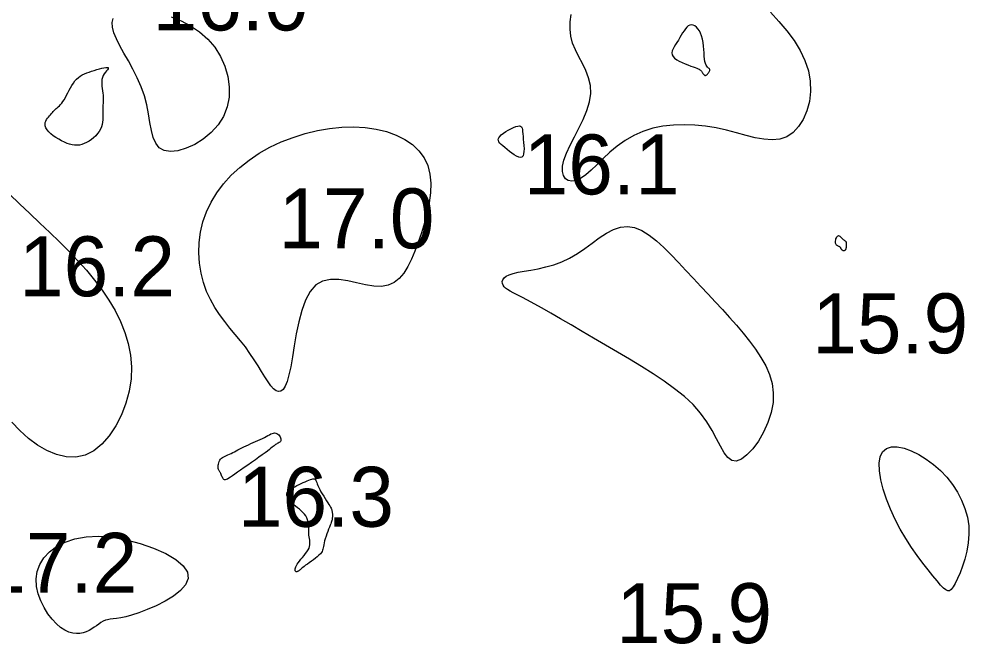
# Model space of a CAD drawing. Extents: x 3040093 to 3056816, y 408076 to 509144.
# Drawn here: x 3045772.1 to 3045851.4, y 434457.7 to 434509.8 of the extents above; entities that cross this region are included whole.
import ezdxf

# ---------------------------------------------------------------- set-up
doc = ezdxf.new("R2010")
doc.units = 0
doc.layers.add('V-CHAN-CONT-EL17', color=7, linetype='Continuous')
doc.layers.add('V-TOPO-SOUN-0610', color=7, linetype='Continuous')

msp = doc.modelspace()

# ---------------------------------------------------------------- linework, layer by layer
at = {"layer": 'V-CHAN-CONT-EL17'}
for points in [[(3045784.771, 434510.028), (3045785.592, 434509.693), (3045786.39, 434509.275), (3045787.141, 434508.769), (3045787.819, 434508.172), (3045788.402, 434507.485), (3045788.881, 434506.722), (3045789.247, 434505.905), (3045789.493, 434505.054), (3045789.613, 434504.19), (3045789.597, 434503.333), (3045789.44, 434502.503), (3045789.133, 434501.722), (3045788.677, 434501.007), (3045788.1, 434500.371), (3045787.44, 434499.827), (3045786.733, 434499.385), (3045786.016, 434499.057), (3045785.325, 434498.854), (3045784.698, 434498.787), (3045784.171, 434498.868), (3045783.769, 434499.102), (3045783.478, 434499.474), (3045783.269, 434499.964), (3045783.117, 434500.55), (3045782.993, 434501.211), (3045782.871, 434501.926), (3045782.724, 434502.675), (3045782.526, 434503.437), (3045782.257, 434504.192), (3045781.93, 434504.933), (3045781.569, 434505.652), (3045781.194, 434506.344), (3045780.827, 434507), (3045780.489, 434507.616), (3045780.204, 434508.185), (3045779.992, 434508.699), (3045779.871, 434509.154), (3045779.847, 434509.548), (3045779.919, 434509.881)], [(3045834.785, 434510.408), (3045835.493, 434509.637), (3045836.154, 434508.847), (3045836.748, 434508.039), (3045837.258, 434507.213), (3045837.665, 434506.371), (3045837.95, 434505.513), (3045838.102, 434504.645), (3045838.124, 434503.785), (3045838.028, 434502.955), (3045837.824, 434502.176), (3045837.522, 434501.471), (3045837.135, 434500.862), (3045836.671, 434500.371), (3045836.142, 434500.02), (3045835.557, 434499.823), (3045834.921, 434499.761), (3045834.238, 434499.808), (3045833.512, 434499.938), (3045832.747, 434500.123), (3045831.946, 434500.338), (3045831.114, 434500.556), (3045830.255, 434500.751), (3045829.373, 434500.899), (3045828.478, 434500.993), (3045827.579, 434501.027), (3045826.686, 434500.996), (3045825.809, 434500.897), (3045824.959, 434500.723), (3045824.145, 434500.471), (3045823.377, 434500.135), (3045822.662, 434499.717), (3045822, 434499.236), (3045821.388, 434498.721), (3045820.821, 434498.196), (3045820.296, 434497.69), (3045819.81, 434497.227), (3045819.36, 434496.836), (3045818.942, 434496.541), (3045818.554, 434496.365), (3045818.206, 434496.307), (3045817.908, 434496.359), (3045817.671, 434496.517), (3045817.505, 434496.774), (3045817.422, 434497.123), (3045817.433, 434497.558), (3045817.547, 434498.073), (3045817.769, 434498.661), (3045818.073, 434499.309), (3045818.427, 434500.001), (3045818.796, 434500.724), (3045819.15, 434501.464), (3045819.454, 434502.206), (3045819.675, 434502.936), (3045819.782, 434503.639), (3045819.751, 434504.304), (3045819.606, 434504.936), (3045819.376, 434505.541), (3045819.096, 434506.127), (3045818.798, 434506.699), (3045818.513, 434507.266), (3045818.274, 434507.834), (3045818.114, 434508.411), (3045818.054, 434509.001), (3045818.079, 434509.603), (3045818.162, 434510.21)], [(3045771.269, 434495.24), (3045772.118, 434494.427), (3045772.968, 434493.62), (3045773.809, 434492.823), (3045774.636, 434492.034), (3045775.442, 434491.249), (3045776.224, 434490.464), (3045776.975, 434489.674), (3045777.691, 434488.875), (3045778.366, 434488.063), (3045778.995, 434487.233), (3045779.572, 434486.383), (3045780.09, 434485.51), (3045780.538, 434484.616), (3045780.907, 434483.7), (3045781.189, 434482.762), (3045781.374, 434481.803), (3045781.453, 434480.821), (3045781.417, 434479.817), (3045781.26, 434478.797), (3045780.99, 434477.783), (3045780.616, 434476.805), (3045780.15, 434475.891), (3045779.602, 434475.071), (3045778.983, 434474.373), (3045778.304, 434473.826), (3045777.574, 434473.46), (3045776.805, 434473.294), (3045776.01, 434473.315), (3045775.204, 434473.503), (3045774.398, 434473.837), (3045773.608, 434474.294), (3045772.847, 434474.855), (3045772.129, 434475.498), (3045771.466, 434476.201)]]:
    msp.add_lwpolyline(points, dxfattribs=at)
for points in [[(3045829.047, 434505.448), (3045829.08, 434505.4), (3045829.114, 434505.349), (3045829.147, 434505.3), (3045829.181, 434505.254), (3045829.214, 434505.213), (3045829.249, 434505.179), (3045829.283, 434505.155), (3045829.318, 434505.141), (3045829.353, 434505.138), (3045829.389, 434505.145), (3045829.425, 434505.16), (3045829.461, 434505.184), (3045829.497, 434505.215), (3045829.533, 434505.253), (3045829.569, 434505.295), (3045829.605, 434505.343), (3045829.638, 434505.394), (3045829.668, 434505.446), (3045829.693, 434505.499), (3045829.71, 434505.55), (3045829.717, 434505.599), (3045829.714, 434505.643), (3045829.697, 434505.682), (3045829.667, 434505.714), (3045829.625, 434505.746), (3045829.575, 434505.783), (3045829.52, 434505.833), (3045829.464, 434505.901), (3045829.409, 434505.996), (3045829.358, 434506.122), (3045829.316, 434506.287), (3045829.284, 434506.494), (3045829.26, 434506.738), (3045829.239, 434507.008), (3045829.216, 434507.295), (3045829.19, 434507.59), (3045829.154, 434507.884), (3045829.105, 434508.167), (3045829.039, 434508.43), (3045828.953, 434508.664), (3045828.85, 434508.867), (3045828.732, 434509.037), (3045828.604, 434509.172), (3045828.469, 434509.271), (3045828.33, 434509.33), (3045828.191, 434509.349), (3045828.056, 434509.326), (3045827.928, 434509.26), (3045827.804, 434509.157), (3045827.685, 434509.021), (3045827.568, 434508.86), (3045827.453, 434508.681), (3045827.337, 434508.488), (3045827.219, 434508.289), (3045827.098, 434508.09), (3045826.973, 434507.896), (3045826.852, 434507.708), (3045826.742, 434507.526), (3045826.652, 434507.351), (3045826.589, 434507.183), (3045826.563, 434507.021), (3045826.582, 434506.867), (3045826.652, 434506.719), (3045826.78, 434506.579), (3045826.957, 434506.447), (3045827.169, 434506.323), (3045827.405, 434506.208), (3045827.651, 434506.102), (3045827.897, 434506.006), (3045828.128, 434505.921), (3045828.334, 434505.848), (3045828.503, 434505.785), (3045828.639, 434505.732), (3045828.746, 434505.686), (3045828.829, 434505.646), (3045828.892, 434505.608), (3045828.941, 434505.572), (3045828.98, 434505.535), (3045829.014, 434505.494)], [(3045774.252, 434500.917), (3045774.238, 434501.063), (3045774.258, 434501.201), (3045774.305, 434501.331), (3045774.371, 434501.452), (3045774.448, 434501.564), (3045774.53, 434501.667), (3045774.61, 434501.761), (3045774.681, 434501.845), (3045774.744, 434501.921), (3045774.802, 434501.991), (3045774.857, 434502.055), (3045774.911, 434502.117), (3045774.967, 434502.177), (3045775.027, 434502.237), (3045775.094, 434502.299), (3045775.168, 434502.364), (3045775.251, 434502.434), (3045775.339, 434502.513), (3045775.433, 434502.602), (3045775.531, 434502.704), (3045775.631, 434502.821), (3045775.734, 434502.956), (3045775.836, 434503.111), (3045775.939, 434503.287), (3045776.042, 434503.48), (3045776.146, 434503.684), (3045776.253, 434503.893), (3045776.364, 434504.102), (3045776.481, 434504.305), (3045776.604, 434504.497), (3045776.735, 434504.672), (3045776.874, 434504.825), (3045777.022, 434504.958), (3045777.18, 434505.074), (3045777.348, 434505.175), (3045777.525, 434505.264), (3045777.713, 434505.344), (3045777.91, 434505.418), (3045778.119, 434505.488), (3045778.337, 434505.557), (3045778.557, 434505.622), (3045778.773, 434505.681), (3045778.976, 434505.731), (3045779.157, 434505.769), (3045779.31, 434505.793), (3045779.426, 434505.799), (3045779.497, 434505.785), (3045779.518, 434505.75), (3045779.496, 434505.693), (3045779.442, 434505.615), (3045779.365, 434505.519), (3045779.275, 434505.406), (3045779.183, 434505.276), (3045779.099, 434505.13), (3045779.032, 434504.971), (3045778.991, 434504.8), (3045778.973, 434504.619), (3045778.973, 434504.431), (3045778.986, 434504.239), (3045779.008, 434504.045), (3045779.034, 434503.852), (3045779.06, 434503.662), (3045779.08, 434503.479), (3045779.09, 434503.305), (3045779.093, 434503.137), (3045779.089, 434502.975), (3045779.081, 434502.816), (3045779.071, 434502.657), (3045779.061, 434502.497), (3045779.053, 434502.334), (3045779.05, 434502.166), (3045779.052, 434501.99), (3045779.056, 434501.809), (3045779.056, 434501.622), (3045779.05, 434501.432), (3045779.032, 434501.239), (3045778.998, 434501.045), (3045778.943, 434500.851), (3045778.863, 434500.658), (3045778.754, 434500.467), (3045778.619, 434500.282), (3045778.464, 434500.106), (3045778.29, 434499.94), (3045778.103, 434499.788), (3045777.907, 434499.652), (3045777.706, 434499.537), (3045777.504, 434499.443), (3045777.304, 434499.375), (3045777.106, 434499.331), (3045776.907, 434499.311), (3045776.706, 434499.315), (3045776.502, 434499.343), (3045776.292, 434499.393), (3045776.076, 434499.465), (3045775.851, 434499.559), (3045775.617, 434499.673), (3045775.38, 434499.805), (3045775.147, 434499.951), (3045774.926, 434500.107), (3045774.724, 434500.27), (3045774.549, 434500.436), (3045774.407, 434500.601), (3045774.306, 434500.762)], [(3045790.545, 434483.006), (3045790.112, 434483.531), (3045789.67, 434484.063), (3045789.231, 434484.61), (3045788.804, 434485.181), (3045788.402, 434485.784), (3045788.037, 434486.427), (3045787.719, 434487.117), (3045787.46, 434487.861), (3045787.264, 434488.651), (3045787.137, 434489.476), (3045787.083, 434490.325), (3045787.109, 434491.188), (3045787.217, 434492.055), (3045787.414, 434492.914), (3045787.704, 434493.756), (3045788.09, 434494.57), (3045788.568, 434495.352), (3045789.131, 434496.097), (3045789.774, 434496.802), (3045790.489, 434497.463), (3045791.272, 434498.076), (3045792.115, 434498.636), (3045793.012, 434499.14), (3045793.956, 434499.583), (3045794.938, 434499.964), (3045795.944, 434500.28), (3045796.964, 434500.527), (3045797.987, 434500.704), (3045799.001, 434500.808), (3045799.995, 434500.836), (3045800.956, 434500.786), (3045801.875, 434500.656), (3045802.74, 434500.447), (3045803.54, 434500.16), (3045804.263, 434499.798), (3045804.9, 434499.361), (3045805.439, 434498.852), (3045805.87, 434498.273), (3045806.18, 434497.624), (3045806.365, 434496.91), (3045806.435, 434496.143), (3045806.408, 434495.338), (3045806.299, 434494.507), (3045806.125, 434493.666), (3045805.902, 434492.829), (3045805.646, 434492.01), (3045805.375, 434491.222), (3045805.099, 434490.481), (3045804.814, 434489.797), (3045804.508, 434489.182), (3045804.171, 434488.647), (3045803.794, 434488.204), (3045803.365, 434487.863), (3045802.875, 434487.636), (3045802.313, 434487.535), (3045801.675, 434487.56), (3045800.978, 434487.676), (3045800.244, 434487.834), (3045799.497, 434487.99), (3045798.76, 434488.097), (3045798.056, 434488.107), (3045797.407, 434487.975), (3045796.836, 434487.654), (3045796.361, 434487.113), (3045795.974, 434486.386), (3045795.662, 434485.52), (3045795.41, 434484.565), (3045795.205, 434483.569), (3045795.035, 434482.582), (3045794.884, 434481.65), (3045794.741, 434480.825), (3045794.593, 434480.143), (3045794.438, 434479.608), (3045794.275, 434479.21), (3045794.103, 434478.941), (3045793.922, 434478.794), (3045793.73, 434478.759), (3045793.528, 434478.829), (3045793.315, 434478.996), (3045793.089, 434479.25), (3045792.848, 434479.581), (3045792.591, 434479.975), (3045792.313, 434480.422), (3045792.014, 434480.907), (3045791.689, 434481.421), (3045791.338, 434481.949), (3045790.956, 434482.48)], [(3045812.321, 434500.173), (3045812.491, 434500.309), (3045812.69, 434500.444), (3045812.904, 434500.574), (3045813.125, 434500.692), (3045813.338, 434500.791), (3045813.535, 434500.866), (3045813.703, 434500.911), (3045813.834, 434500.921), (3045813.932, 434500.896), (3045814.001, 434500.836), (3045814.048, 434500.743), (3045814.079, 434500.617), (3045814.1, 434500.46), (3045814.116, 434500.272), (3045814.134, 434500.054), (3045814.157, 434499.809), (3045814.182, 434499.547), (3045814.203, 434499.281), (3045814.215, 434499.024), (3045814.21, 434498.787), (3045814.184, 434498.584), (3045814.132, 434498.426), (3045814.046, 434498.326), (3045813.924, 434498.292), (3045813.771, 434498.319), (3045813.594, 434498.393), (3045813.401, 434498.505), (3045813.199, 434498.644), (3045812.995, 434498.799), (3045812.798, 434498.958), (3045812.613, 434499.111), (3045812.449, 434499.25), (3045812.309, 434499.374), (3045812.197, 434499.489), (3045812.117, 434499.598), (3045812.073, 434499.704), (3045812.068, 434499.811), (3045812.105, 434499.923), (3045812.189, 434500.042)], [(3045818.665, 434490.269), (3045819.289, 434490.698), (3045819.898, 434491.145), (3045820.497, 434491.578), (3045821.087, 434491.965), (3045821.674, 434492.276), (3045822.26, 434492.478), (3045822.85, 434492.541), (3045823.445, 434492.441), (3045824.046, 434492.194), (3045824.653, 434491.82), (3045825.264, 434491.343), (3045825.878, 434490.784), (3045826.494, 434490.168), (3045827.112, 434489.515), (3045827.731, 434488.849), (3045828.349, 434488.188), (3045828.965, 434487.534), (3045829.577, 434486.885), (3045830.182, 434486.239), (3045830.778, 434485.593), (3045831.363, 434484.945), (3045831.936, 434484.294), (3045832.493, 434483.638), (3045833.031, 434482.973), (3045833.536, 434482.297), (3045833.993, 434481.607), (3045834.385, 434480.9), (3045834.697, 434480.173), (3045834.914, 434479.423), (3045835.019, 434478.646), (3045834.997, 434477.84), (3045834.84, 434477.007), (3045834.566, 434476.174), (3045834.201, 434475.373), (3045833.772, 434474.635), (3045833.304, 434473.993), (3045832.823, 434473.479), (3045832.356, 434473.124), (3045831.928, 434472.962), (3045831.558, 434473.013), (3045831.231, 434473.256), (3045830.926, 434473.659), (3045830.62, 434474.191), (3045830.292, 434474.819), (3045829.919, 434475.512), (3045829.48, 434476.238), (3045828.953, 434476.966), (3045828.322, 434477.669), (3045827.595, 434478.345), (3045826.786, 434478.997), (3045825.91, 434479.631), (3045824.98, 434480.249), (3045824.011, 434480.854), (3045823.017, 434481.452), (3045822.012, 434482.046), (3045821.011, 434482.637), (3045820.024, 434483.219), (3045819.064, 434483.784), (3045818.142, 434484.326), (3045817.269, 434484.834), (3045816.458, 434485.302), (3045815.719, 434485.721), (3045815.064, 434486.084), (3045814.502, 434486.386), (3045814.028, 434486.632), (3045813.632, 434486.834), (3045813.307, 434487), (3045813.046, 434487.141), (3045812.838, 434487.267), (3045812.677, 434487.386), (3045812.554, 434487.51), (3045812.463, 434487.644), (3045812.41, 434487.789), (3045812.402, 434487.938), (3045812.446, 434488.089), (3045812.551, 434488.237), (3045812.724, 434488.377), (3045812.972, 434488.506), (3045813.304, 434488.62), (3045813.724, 434488.716), (3045814.22, 434488.805), (3045814.779, 434488.9), (3045815.387, 434489.012), (3045816.029, 434489.155), (3045816.692, 434489.34), (3045817.361, 434489.58), (3045818.023, 434489.888)], [(3045840.491, 434490.866), (3045840.447, 434490.885), (3045840.399, 434490.908), (3045840.351, 434490.937), (3045840.306, 434490.974), (3045840.267, 434491.019), (3045840.235, 434491.076), (3045840.215, 434491.145), (3045840.207, 434491.227), (3045840.211, 434491.319), (3045840.226, 434491.414), (3045840.251, 434491.508), (3045840.284, 434491.595), (3045840.325, 434491.67), (3045840.37, 434491.727), (3045840.421, 434491.762), (3045840.474, 434491.77), (3045840.529, 434491.755), (3045840.585, 434491.722), (3045840.642, 434491.675), (3045840.698, 434491.62), (3045840.753, 434491.561), (3045840.805, 434491.504), (3045840.854, 434491.452), (3045840.899, 434491.411), (3045840.939, 434491.378), (3045840.975, 434491.352), (3045841.007, 434491.33), (3045841.035, 434491.31), (3045841.057, 434491.29), (3045841.076, 434491.267), (3045841.09, 434491.24), (3045841.1, 434491.206), (3045841.105, 434491.166), (3045841.108, 434491.122), (3045841.108, 434491.074), (3045841.106, 434491.025), (3045841.103, 434490.975), (3045841.1, 434490.926), (3045841.097, 434490.878), (3045841.094, 434490.834), (3045841.092, 434490.793), (3045841.09, 434490.755), (3045841.086, 434490.72), (3045841.081, 434490.687), (3045841.074, 434490.657), (3045841.064, 434490.628), (3045841.05, 434490.603), (3045841.033, 434490.579), (3045841.012, 434490.557), (3045840.988, 434490.539), (3045840.962, 434490.524), (3045840.935, 434490.514), (3045840.906, 434490.509), (3045840.877, 434490.509), (3045840.849, 434490.515), (3045840.821, 434490.528), (3045840.794, 434490.546), (3045840.768, 434490.568), (3045840.744, 434490.594), (3045840.722, 434490.621), (3045840.702, 434490.649), (3045840.684, 434490.677), (3045840.669, 434490.703), (3045840.656, 434490.727), (3045840.645, 434490.748), (3045840.634, 434490.767), (3045840.621, 434490.785), (3045840.606, 434490.802), (3045840.587, 434490.818), (3045840.562, 434490.834), (3045840.531, 434490.85)], [(3045789.163, 434471.428), (3045789.115, 434471.475), (3045789.075, 434471.537), (3045789.039, 434471.608), (3045789.007, 434471.686), (3045788.977, 434471.765), (3045788.947, 434471.841), (3045788.917, 434471.91), (3045788.885, 434471.969), (3045788.852, 434472.019), (3045788.819, 434472.065), (3045788.787, 434472.108), (3045788.757, 434472.153), (3045788.731, 434472.203), (3045788.71, 434472.261), (3045788.694, 434472.33), (3045788.686, 434472.412), (3045788.686, 434472.506), (3045788.694, 434472.607), (3045788.711, 434472.713), (3045788.739, 434472.819), (3045788.778, 434472.924), (3045788.829, 434473.023), (3045788.892, 434473.113), (3045788.968, 434473.192), (3045789.056, 434473.261), (3045789.155, 434473.323), (3045789.263, 434473.379), (3045789.38, 434473.432), (3045789.503, 434473.485), (3045789.632, 434473.54), (3045789.766, 434473.599), (3045789.903, 434473.664), (3045790.043, 434473.735), (3045790.189, 434473.811), (3045790.34, 434473.891), (3045790.497, 434473.974), (3045790.662, 434474.06), (3045790.834, 434474.148), (3045791.016, 434474.237), (3045791.207, 434474.327), (3045791.404, 434474.416), (3045791.604, 434474.505), (3045791.805, 434474.594), (3045792.003, 434474.682), (3045792.195, 434474.768), (3045792.377, 434474.853), (3045792.547, 434474.936), (3045792.703, 434475.017), (3045792.844, 434475.093), (3045792.973, 434475.161), (3045793.091, 434475.22), (3045793.2, 434475.265), (3045793.302, 434475.294), (3045793.398, 434475.305), (3045793.489, 434475.294), (3045793.578, 434475.261), (3045793.662, 434475.208), (3045793.738, 434475.14), (3045793.805, 434475.061), (3045793.86, 434474.975), (3045793.9, 434474.888), (3045793.924, 434474.803), (3045793.928, 434474.724), (3045793.911, 434474.655), (3045793.876, 434474.596), (3045793.826, 434474.545), (3045793.766, 434474.499), (3045793.697, 434474.457), (3045793.625, 434474.417), (3045793.552, 434474.378), (3045793.482, 434474.337), (3045793.417, 434474.294), (3045793.352, 434474.244), (3045793.281, 434474.185), (3045793.197, 434474.114), (3045793.094, 434474.028), (3045792.966, 434473.923), (3045792.806, 434473.798), (3045792.608, 434473.648), (3045792.368, 434473.472), (3045792.093, 434473.276), (3045791.795, 434473.065), (3045791.482, 434472.847), (3045791.167, 434472.627), (3045790.858, 434472.412), (3045790.565, 434472.208), (3045790.3, 434472.023), (3045790.071, 434471.861), (3045789.875, 434471.723), (3045789.71, 434471.61), (3045789.571, 434471.521), (3045789.457, 434471.455), (3045789.362, 434471.413), (3045789.283, 434471.395), (3045789.218, 434471.4)], [(3045844.8, 434468.936), (3045844.467, 434469.783), (3045844.197, 434470.613), (3045844.001, 434471.404), (3045843.887, 434472.134), (3045843.867, 434472.781), (3045843.95, 434473.323), (3045844.145, 434473.737), (3045844.458, 434474.006), (3045844.873, 434474.138), (3045845.371, 434474.142), (3045845.931, 434474.032), (3045846.534, 434473.819), (3045847.159, 434473.514), (3045847.785, 434473.129), (3045848.394, 434472.676), (3045848.968, 434472.166), (3045849.496, 434471.606), (3045849.972, 434471.003), (3045850.389, 434470.363), (3045850.741, 434469.693), (3045851.02, 434469), (3045851.219, 434468.29), (3045851.331, 434467.571), (3045851.354, 434466.849), (3045851.298, 434466.136), (3045851.18, 434465.446), (3045851.015, 434464.789), (3045850.819, 434464.18), (3045850.607, 434463.63), (3045850.396, 434463.152), (3045850.199, 434462.758), (3045850.03, 434462.459), (3045849.879, 434462.256), (3045849.735, 434462.147), (3045849.586, 434462.13), (3045849.42, 434462.204), (3045849.224, 434462.367), (3045848.987, 434462.618), (3045848.696, 434462.955), (3045848.344, 434463.376), (3045847.939, 434463.874), (3045847.497, 434464.443), (3045847.029, 434465.075), (3045846.551, 434465.763), (3045846.075, 434466.501), (3045845.616, 434467.281), (3045845.186, 434468.096)], [(3045795.332, 434463.76), (3045795.291, 434463.741), (3045795.254, 434463.73), (3045795.219, 434463.726), (3045795.188, 434463.731), (3045795.162, 434463.745), (3045795.141, 434463.768), (3045795.125, 434463.801), (3045795.115, 434463.845), (3045795.114, 434463.9), (3045795.121, 434463.966), (3045795.141, 434464.044), (3045795.174, 434464.133), (3045795.222, 434464.235), (3045795.288, 434464.349), (3045795.372, 434464.476), (3045795.476, 434464.615), (3045795.595, 434464.764), (3045795.722, 434464.92), (3045795.852, 434465.08), (3045795.978, 434465.242), (3045796.093, 434465.402), (3045796.192, 434465.557), (3045796.269, 434465.705), (3045796.318, 434465.843), (3045796.344, 434465.974), (3045796.351, 434466.101), (3045796.343, 434466.227), (3045796.326, 434466.355), (3045796.304, 434466.487), (3045796.282, 434466.628), (3045796.265, 434466.78), (3045796.256, 434466.945), (3045796.252, 434467.12), (3045796.249, 434467.304), (3045796.242, 434467.491), (3045796.228, 434467.68), (3045796.2, 434467.867), (3045796.155, 434468.048), (3045796.089, 434468.22), (3045795.998, 434468.381), (3045795.886, 434468.531), (3045795.756, 434468.674), (3045795.614, 434468.809), (3045795.463, 434468.94), (3045795.308, 434469.068), (3045795.154, 434469.195), (3045795.004, 434469.322), (3045794.863, 434469.451), (3045794.735, 434469.582), (3045794.624, 434469.713), (3045794.534, 434469.843), (3045794.468, 434469.97), (3045794.43, 434470.095), (3045794.424, 434470.215), (3045794.455, 434470.33), (3045794.523, 434470.439), (3045794.625, 434470.542), (3045794.755, 434470.64), (3045794.907, 434470.733), (3045795.074, 434470.823), (3045795.253, 434470.91), (3045795.435, 434470.994), (3045795.616, 434471.078), (3045795.79, 434471.159), (3045795.955, 434471.238), (3045796.109, 434471.31), (3045796.252, 434471.373), (3045796.382, 434471.425), (3045796.498, 434471.463), (3045796.597, 434471.484), (3045796.679, 434471.486), (3045796.744, 434471.466), (3045796.795, 434471.424), (3045796.837, 434471.362), (3045796.875, 434471.28), (3045796.913, 434471.178), (3045796.957, 434471.058), (3045797.011, 434470.919), (3045797.08, 434470.763), (3045797.167, 434470.59), (3045797.269, 434470.406), (3045797.381, 434470.215), (3045797.499, 434470.023), (3045797.618, 434469.834), (3045797.733, 434469.653), (3045797.839, 434469.486), (3045797.932, 434469.338), (3045798.007, 434469.213), (3045798.067, 434469.108), (3045798.112, 434469.019), (3045798.146, 434468.945), (3045798.17, 434468.88), (3045798.186, 434468.822), (3045798.197, 434468.767), (3045798.205, 434468.712), (3045798.211, 434468.653), (3045798.216, 434468.592), (3045798.219, 434468.53), (3045798.221, 434468.466), (3045798.222, 434468.403), (3045798.221, 434468.342), (3045798.219, 434468.282), (3045798.215, 434468.226), (3045798.21, 434468.174), (3045798.201, 434468.123), (3045798.189, 434468.068), (3045798.172, 434468.005), (3045798.149, 434467.932), (3045798.118, 434467.844), (3045798.079, 434467.736), (3045798.031, 434467.606), (3045797.972, 434467.45), (3045797.906, 434467.274), (3045797.836, 434467.083), (3045797.765, 434466.884), (3045797.695, 434466.683), (3045797.631, 434466.485), (3045797.575, 434466.298), (3045797.531, 434466.127), (3045797.499, 434465.977), (3045797.477, 434465.845), (3045797.458, 434465.728), (3045797.436, 434465.62), (3045797.407, 434465.52), (3045797.364, 434465.422), (3045797.302, 434465.322), (3045797.216, 434465.216), (3045797.1, 434465.102), (3045796.961, 434464.981), (3045796.805, 434464.856), (3045796.637, 434464.73), (3045796.465, 434464.604), (3045796.295, 434464.483), (3045796.134, 434464.368), (3045795.988, 434464.263), (3045795.862, 434464.169), (3045795.755, 434464.086), (3045795.665, 434464.014), (3045795.588, 434463.952), (3045795.524, 434463.899), (3045795.468, 434463.854), (3045795.419, 434463.816), (3045795.374, 434463.785)], [(3045773.801, 434464.334), (3045774.145, 434464.891), (3045774.615, 434465.398), (3045775.206, 434465.841), (3045775.914, 434466.206), (3045776.736, 434466.478), (3045777.668, 434466.643), (3045778.705, 434466.687), (3045779.834, 434466.601), (3045781.013, 434466.397), (3045782.186, 434466.093), (3045783.302, 434465.707), (3045784.308, 434465.256), (3045785.151, 434464.759), (3045785.777, 434464.233), (3045786.134, 434463.696), (3045786.186, 434463.164), (3045785.971, 434462.648), (3045785.541, 434462.154), (3045784.951, 434461.69), (3045784.254, 434461.266), (3045783.505, 434460.888), (3045782.756, 434460.566), (3045782.063, 434460.305), (3045781.467, 434460.113), (3045780.968, 434459.978), (3045780.552, 434459.888), (3045780.206, 434459.831), (3045779.918, 434459.794), (3045779.675, 434459.764), (3045779.463, 434459.728), (3045779.271, 434459.674), (3045779.086, 434459.592), (3045778.904, 434459.486), (3045778.722, 434459.362), (3045778.536, 434459.228), (3045778.342, 434459.09), (3045778.137, 434458.956), (3045777.918, 434458.831), (3045777.681, 434458.723), (3045777.424, 434458.639), (3045777.148, 434458.587), (3045776.854, 434458.574), (3045776.545, 434458.609), (3045776.221, 434458.698), (3045775.885, 434458.85), (3045775.538, 434459.073), (3045775.183, 434459.375), (3045774.823, 434459.759), (3045774.474, 434460.217), (3045774.153, 434460.734), (3045773.878, 434461.297), (3045773.666, 434461.893), (3045773.535, 434462.508), (3045773.503, 434463.129), (3045773.587, 434463.742)]]:
    msp.add_lwpolyline(points, close=True, dxfattribs=at)

# ---------------------------------------------------------------- texts
at = {"layer": 'V-TOPO-SOUN-0610'}
for s, p in [('16.0 ', (3045783.223, 434508.89)), ('16.1 ', (3045814.193, 434495.21)), ('17.0 ', (3045793.723, 434490.71)), ('16.2 ', (3045772.073, 434486.71)), ('15.9 ', (3045838.273, 434481.95)), ('16.3 ', (3045790.343, 434467.48)), ('17.2 ', (3045768.923, 434461.97)), ('15.9 ', (3045821.903, 434457.77))]:
    msp.add_text(s, height=5, dxfattribs=at).set_placement(p)

doc.saveas('drawing.dxf')
